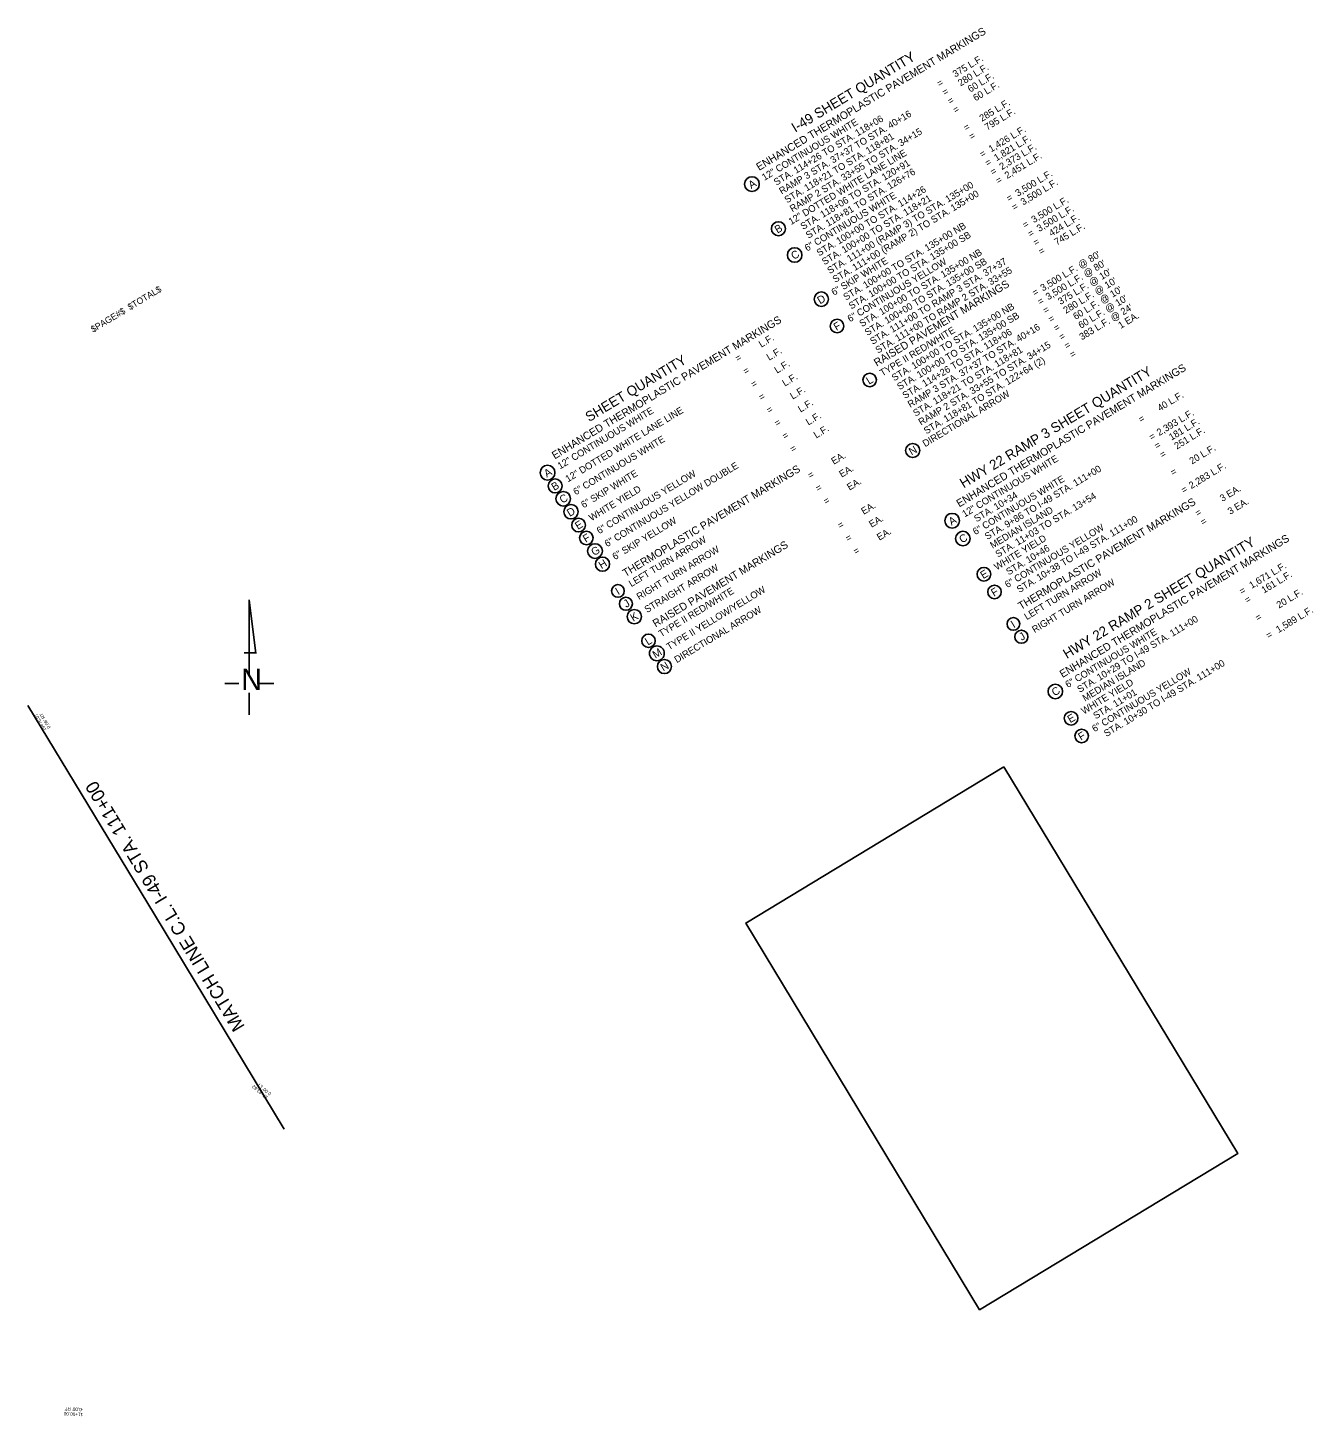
# Model space of a CAD drawing. Extents: x 627805 to 632137, y 367199 to 370341.
# Drawn here: x 629804 to 632137, y 367820 to 370341 of the extents above; entities that cross this region are included whole.
import ezdxf

# ---------------------------------------------------------------- set-up
doc = ezdxf.new("R2010")
doc.units = 0
for name, color, linetype in [('B_Subtitle_Text', 7, 'Continuous'), ('B_Title_Text', 7, 'Continuous'), ('R_Border', 7, 'Continuous'), ('R_Border_N Arrow', 7, 'Continuous'), ('R_Dimension', 7, 'Continuous'), ('R_Draft', 7, 'Continuous'), ('R_No Plot', 7, 'Continuous')]:
    doc.layers.add(name, color=color, linetype=linetype)

msp = doc.modelspace()

# ---------------------------------------------------------------- linework, layer by layer
at = {"layer": 'B_Subtitle_Text'}
for centre, radius in [((631118.6, 370056.9), 13.4), ((631166.7, 369976), 12.7), ((631196.2, 369928.2), 13.2), ((631244.6, 369848.1), 13.1), ((631273.1, 369799.3), 12.3), ((631332.3, 369701.4), 12.2), ((631410.4, 369573.4), 12.8), ((630747.7, 369533.1), 13.4), ((630761.5, 369509), 12.7), ((630776.2, 369485.8), 13.2), ((630790.3, 369462.3), 13.1), ((630804.1, 369438.1), 12.4), ((631482, 369445.9), 13.4), ((630818.2, 369414.6), 12.3), ((631501.4, 369413.5), 13.2), ((630833.8, 369390.8), 13.4), ((630847.5, 369367.1), 12.9), ((631539.7, 369348.7), 12.4), ((630875.4, 369318.4), 11.5), ((631558.9, 369316.7), 12.3), ((630889.9, 369295.2), 11.9), ((630905.2, 369271.8), 12.9), ((631593.1, 369258.6), 11.5), ((630930.9, 369228), 12.2), ((631607.6, 369235.4), 11.9), ((630946.1, 369205.2), 13.5), ((630959.8, 369181.3), 12.8), ((631669.2, 369136), 13.2), ((631697.8, 369087.3), 12.4), ((631717, 369055.2), 12.3)]:
    msp.add_circle(centre, radius, dxfattribs=at)
at = {"layer": 'R_Border_N Arrow'}
for p, q in [((630206.5, 369302.1), (630218.6, 369205.2)), ((630206.5, 369166.6), (630206.5, 369302.1)), ((630197.1, 369205.9), (630218.7, 369205.9)), ((630161.9, 369150.6), (630187.6, 369150.6)), ((630223.6, 369150.6), (630251.1, 369150.6)), ((630206.5, 369093.8), (630206.5, 369133.7))]:
    msp.add_line(p, q, dxfattribs=at)
at = {"layer": 'R_Dimension'}
msp.add_lwpolyline([(631575.7, 368999), (631107.3, 368715.7), (631531.7, 368013.9), (632000.2, 368297.2)], close=True, dxfattribs=at)
at = {"layer": 'R_Draft'}
msp.add_lwpolyline([(630269.5, 368341.8), (630034.2, 368730.9), (629804.5, 369110.8)], dxfattribs=at)

# ---------------------------------------------------------------- texts
at = {"layer": 'B_Subtitle_Text'}
for s, p in [('ENHANCED THERMOPLASTIC PAVEMENT MARKINGS', (631131.7, 370080.8)), ('A', (631117.3, 370047.9)), ('B', (631165, 369966.9)), ('C', (631194.7, 369919.2)), ('RAISED PAVEMENT MARKINGS', (631345.1, 369725.5)), ('D', (631242.3, 369838.5)), ('ENHANCED THERMOPLASTIC PAVEMENT MARKINGS', (630760.8, 369557.1)), ('F', (631272, 369790.4)), ('ENHANCED THERMOPLASTIC PAVEMENT MARKINGS', (631495, 369469.9)), ('L', (631331.2, 369692.6)), ('N', (631408.5, 369564.1)), ('THERMOPLASTIC PAVEMENT MARKINGS', (630889.2, 369343.5)), ('A', (630746.4, 369524.1)), ('B', (630759.8, 369499.8)), ('C', (630774.7, 369476.7)), ('D', (630788, 369452.7)), ('THERMOPLASTIC PAVEMENT MARKINGS', (631606.9, 369283.7)), ('E', (630802.8, 369429.1)), ('A', (631480.7, 369436.9)), ('F', (630817, 369405.7)), ('C', (631499.9, 369404.5)), ('ENHANCED THERMOPLASTIC PAVEMENT MARKINGS', (631682.3, 369160.3)), ('G', (630832.1, 369381.6)), ('RAISED PAVEMENT MARKINGS', (630943.7, 369252.1)), ('H', (630845.6, 369357.8)), ('E', (631538.3, 369339.7)), ('I', (630875.9, 369310.6)), ('F', (631557.7, 369307.8)), ('J', (630890.6, 369287.6)), ('K', (630903.2, 369262.4)), ('I', (631593.6, 369250.8)), ('J', (631608.3, 369227.7)), ('L', (630929.8, 369219.2)), ('M', (630943.4, 369195.4)), ('N', (630957.9, 369172)), ('C', (631667.7, 369127)), ('E', (631696.4, 369078.3)), ('F', (631715.8, 369046.4))]:
    msp.add_text(s, height=14, rotation=31.1638, dxfattribs=at).set_placement(p)
at = {"layer": 'B_Title_Text'}
for s, p in [('I-49 SHEET QUANTITY', (631197.2, 370150.1)), ('SHEET QUANTITY', (630823.2, 369624.8)), ('HWY 22 RAMP 3 SHEET QUANTITY', (631502.8, 369504.5)), ('HWY 22 RAMP 2 SHEET QUANTITY', (631690.1, 369194.7))]:
    msp.add_text(s, height=18, rotation=31.1638, dxfattribs=at).set_placement(p)
at = {"layer": 'R_Border'}
for s, p in [('$TOTAL$', (629990.2, 369827.7)), ('$PAGE#$', (629923.3, 369787.2))]:
    msp.add_text(s, height=11.72, rotation=31.1638, dxfattribs=at).set_placement(p)
at = {"layer": 'R_Border_N Arrow'}
msp.add_text('N', height=38.8, rotation=360, dxfattribs=at).set_placement((630191.8, 369138.6))
at = {"layer": 'R_Dimension'}
for s, p in [('375 L.F.', (631487.5, 370250.2)), ('280 L.F.', (631497.2, 370234.1)), ('60 L.F.', (631514.9, 370222.9)), ('=', (631458.9, 370232.8)), ('=', (631468.6, 370216.8)), ('60 L.F.', (631524.6, 370206.9)), ('=', (631478.3, 370200.8)), ('285 L.F.', (631536, 370169.9)), ('12" CONTINUOUS WHITE', (631141.3, 370062.7)), ('   STA. 114+26 TO STA. 118+06', (631151, 370046.7)), ('   RAMP 3 STA. 37+37 TO STA. 40+16', (631160.7, 370030.6)), ('=', (631488, 370184.7)), ('795 L.F.', (631545.7, 370153.9)), ('   STA. 118+21 TO STA. 118+81', (631170.4, 370014.6)), ('   RAMP 2 STA. 33+55 TO STA. 34+15', (631180.1, 369998.5)), ('=', (631507.4, 370152.6)), ('=', (631517.1, 370136.6)), ('1,426 L.F.', (631552.7, 370114.3)), ('1,821 L.F.', (631562.4, 370098.2)), ('2,373 L.F.', (631572.1, 370082.2)), ('12" DOTTED WHITE LANE LINE', (631189.8, 369982.5)), ('   STA. 118+06 TO STA. 120+91', (631199.5, 369966.4)), ('=', (631536.5, 370104.5)), ('=', (631546.2, 370088.5)), ('2,451 L.F.', (631581.8, 370066.1)), ('   STA. 118+81 TO STA. 126+76', (631209.2, 369950.4)), ('=', (631555.9, 370072.4)), ('3,500 L.F.', (631601.2, 370034)), ('   STA. 100+00 TO STA. 114+26', (631228.6, 369918.3)), ('   STA. 111+00 (RAMP 3) TO STA. 135+00', (631248, 369886.2)), ('=', (631565.6, 370056.4)), ('3,500 L.F.', (631610.9, 370018)), ('6" CONTINUOUS WHITE', (631218.9, 369934.3)), ('   STA. 100+00 TO STA. 118+21', (631238.3, 369902.3)), ('   STA. 111+00 (RAMP 2) TO STA. 135+00', (631257.7, 369870.2)), ('=', (631585, 370024.3)), ('3,500 L.F.', (631630.3, 369985.9)), ('=', (631594.7, 370008.2)), ('3,500 L.F.', (631640, 369969.9)), ('424 L.F.', (631662.2, 369961.4)), ('   STA. 100+00 TO STA. 135+00 NB', (631277.2, 369838.1)), ('   STA. 100+00 TO STA. 135+00 SB', (631286.9, 369822)), ('=', (631614.1, 369976.1)), ('=', (631623.8, 369960.1)), ('745 L.F.', (631671.9, 369945.3)), ('=', (631633.6, 369944.1)), ('6" SKIP WHITE', (631267.4, 369854.1)), ('6" CONTINUOUS YELLOW', (631296.6, 369806)), ('   STA. 100+00 TO STA. 135+00 NB', (631306.3, 369789.9)), ('   STA. 100+00 TO STA. 135+00 SB', (631316, 369773.9)), ('   STA. 111+00 TO RAMP 3 STA. 37+37', (631325.7, 369757.9)), ('=', (631643.3, 369928)), ("3,500 L.F. @ 80'", (631646.7, 369861.9)), ('   STA. 111+00 TO RAMP 2 STA. 33+55', (631335.4, 369741.8)), ("3,500 L.F. @ 80'", (631656.4, 369845.9)), ("375 L.F. @ 10'", (631678.6, 369837.4)), ("280 L.F. @ 10'", (631688.3, 369821.3)), ("60 L.F. @ 10'", (631706, 369810.1)), ('= ', (631631.9, 369853)), ('=', (631641.6, 369836.9)), ("60 L.F. @ 10'", (631715.7, 369794.1)), ('   STA. 100+00 TO STA. 135+00 NB', (631365, 369691.6)), ('   STA. 100+00 TO STA. 135+00 SB', (631374.7, 369675.5)), ('=', (631651.3, 369820.9)), ("383 L.F. @ 24'", (631717.4, 369773.2)), ('1 EA.', (631787.9, 369793.9)), ('TYPE II RED/WHITE', (631355.3, 369707.6)), ('   STA. 114+26 TO STA. 118+06', (631384.4, 369659.5)), ('   RAMP 3 STA. 37+37 TO STA. 40+16', (631394.1, 369643.4)), ('=', (631661, 369804.8)), ('=', (631670.7, 369788.8)), ('L.F.', (631135.6, 369759.8)), ('   RAMP 2 STA. 33+55 TO STA. 34+15', (631413.5, 369611.3)), ('=', (631680.4, 369772.7)), ('=', (631092.8, 369733.9)), ('L.F.', (631149.8, 369736.2)), ('   STA. 118+21 TO STA. 118+81', (631403.8, 369627.4)), ('=', (631690.1, 369756.7)), ('=', (631699.8, 369740.7)), ('=', (631107, 369710.4)), ('L.F.', (631164.1, 369712.7)), ('   STA. 118+81 TO STA. 122+64 (2)', (631423.2, 369595.3)), ('=', (631121.3, 369686.8)), ('L.F.', (631178.3, 369689.2)), ('=', (631135.5, 369663.3)), ('L.F.', (631192.5, 369665.6)), ('DIRECTIONAL ARROW', (631432.9, 369579.3)), ('40 L.F.', (631858.9, 369644)), ('12" CONTINUOUS WHITE', (630770.4, 369538.9)), ('12" DOTTED WHITE LANE LINE', (630784.7, 369515.4)), ('=', (631149.7, 369639.8)), ('L.F.', (631206.8, 369642.1)), ('2,393 L.F.', (631857.8, 369599.5)), ('=', (631164, 369616.2)), ('L.F.', (631221, 369618.6)), ('=', (631824.5, 369623.2)), ('181 L.F.', (631880, 369591.1)), ('6" CONTINUOUS WHITE', (630798.9, 369491.9)), ('=', (631178.2, 369592.7)), ('L.F.', (631235.2, 369595)), ('= ', (631843.9, 369591.1)), ('251 L.F.', (631889.7, 369575)), ('=', (631192.4, 369569.2)), ('=', (631853.6, 369575.1)), ('=', (631863.3, 369559)), ('20 L.F.', (631917.1, 369547.8)), ('6" CONTINUOUS YELLOW DOUBLE', (630855.8, 369397.7)), ('EA.', (631267.2, 369547.4)), ('EA.', (631281.5, 369523.9)), ('12" CONTINUOUS WHITE', (631504.7, 369451.7)), ('   STA. 9+86 TO I-49 STA. 111+00', (631533.8, 369403.6)), ('2,283 L.F.', (631916, 369503.3)), ('6" SKIP WHITE', (630813.1, 369468.3)), ('6" CONTINUOUS YELLOW', (630841.6, 369421.3)), ('=', (631224.5, 369521.6)), ('EA.', (631295.7, 369500.4)), ('6" CONTINUOUS WHITE', (631524.1, 369419.6)), ('=', (631882.7, 369526.9)), ('WHITE YIELD', (630827.4, 369444.8)), ('=', (631238.7, 369498)), ('   STA. 10+34', (631514.4, 369435.7)), ('   STA. 11+03 TO STA. 13+54', (631553.2, 369371.5)), ('=', (631902.1, 369494.8)), ('3 EA.', (631972.3, 369480)), ('=', (631252.9, 369474.5)), ('EA.', (631321.5, 369456.5)), ('   MEDIAN ISLAND', (631543.5, 369387.6)), ('3 EA.', (631986.6, 369456.5)), ('6" SKIP YELLOW', (630870, 369374.2)), ('= ', (631278.7, 369430.7)), ('EA.', (631335.7, 369433)), ('   STA. 10+38 TO I-49 STA. 111+00', (631592, 369307.3)), ('=', (631927.5, 369452.9)), ('=', (631937.2, 369436.8)), ('LEFT TURN ARROW', (630899.7, 369325.2)), ('=', (631292.9, 369407.1)), ('EA.', (631349.9, 369409.5)), ('WHITE YIELD', (631562.9, 369355.5)), ('6" CONTINUOUS YELLOW', (631582.3, 369323.4)), ('RIGHT TURN ARROW', (630913.9, 369301.6)), ('=', (631307.2, 369383.6)), ('   STA. 10+46', (631572.6, 369339.4)), ('STRAIGHT ARROW', (630928.2, 369278.1)), ('1,671 L.F.', (632025.6, 369322.1)), ('LEFT TURN ARROW', (631617.4, 369265.3)), ('RIGHT TURN ARROW', (631631.6, 369241.8)), ('161 L.F.', (632047.8, 369313.6)), ('TYPE II RED/WHITE', (630953.9, 369234.3)), ('TYPE II YELLOW/YELLOW', (630968.2, 369210.7)), ('= ', (632007.7, 369311.2)), ('20 L.F.', (632075.2, 369286.3)), ('DIRECTIONAL ARROW', (630982.4, 369187.2)), ('=', (632017.4, 369295.2)), ('   STA. 10+29 TO I-49 STA. 111+00', (631701.6, 369126.1)), ('=', (632036.8, 369263.1)), ('1,589 L.F.', (632074.1, 369241.8)), ('6" CONTINUOUS WHITE', (631691.9, 369142.1)), ('=', (632056.2, 369231)), ('   MEDIAN ISLAND', (631711.3, 369110.1)), ('   STA. 10+30 TO I-49 STA. 111+00', (631750.1, 369045.9)), ('6" CONTINUOUS YELLOW', (631740.4, 369061.9)), ('WHITE YIELD', (631721, 369094)), ('   STA. 11+01', (631730.7, 369078))]:
    msp.add_text(s, height=12.5, rotation=31.1638, dxfattribs=at).set_placement(p)
at = {"layer": 'R_Draft'}
msp.add_text('MATCH LINE C.L. I-49 STA. 111+00', height=24, rotation=121.1638, dxfattribs=at).set_placement((630199, 368528))
at = {"layer": 'R_No Plot'}
for s, rotation, p in [('19+76.07 ', 119.4694, (629838.4, 369066.3)), ("0.06' RT  ", 119.4694, (629846.2, 369070.7)), ('17+83.62 ', 140.0435, (630241.1, 368399.8)), ("0.00' LT  ", 140.0435, (630246.8, 368406.7)), ("-0.00' RT  ", 177.2822, (629905.3, 367835.4)), ('11+00.00 ', 177.2822, (629904.8, 367826.4))]:
    msp.add_text(s, height=6, rotation=rotation, dxfattribs=at).set_placement(p)

doc.saveas('drawing.dxf')
